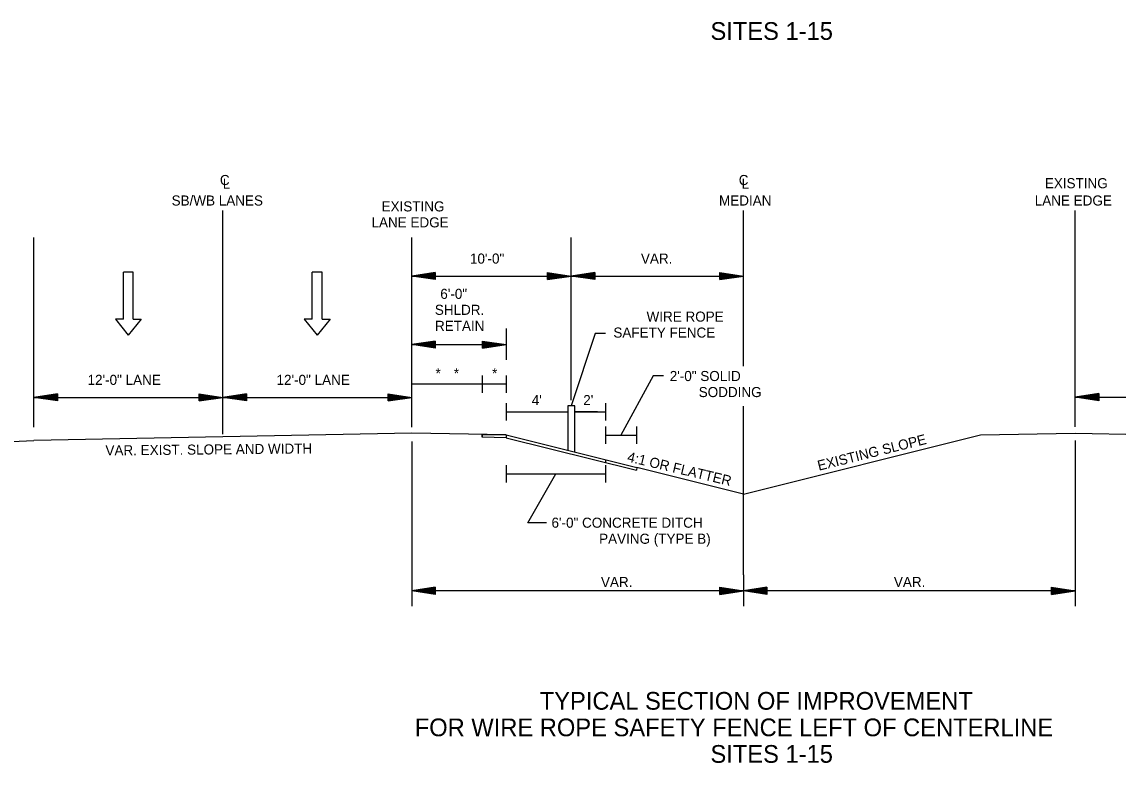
# Model space of a CAD drawing. Extents: x 1641422 to 1649187, y 577497 to 580642.
# Drawn here: x 1645133 to 1646438, y 578840 to 579722 of the extents above; entities that cross this region are included whole.
import ezdxf

# ---------------------------------------------------------------- set-up
doc = ezdxf.new("R2010")
doc.units = 0
doc.layers.add('Default', color=7, linetype='Continuous')
doc.layers.add('R_Draft', color=7, linetype='Continuous')

msp = doc.modelspace()

# ---------------------------------------------------------------- linework, layer by layer
at = {"layer": 'Default'}
for p, q in [((1645790.8, 579264.9), (1645782.7, 579264.9)), ((1645782.7, 579264.9), (1645782.7, 579211.8)), ((1645782.7, 579261.9), (1645782.7, 579254.7)), ((1645790.8, 579209.7), (1645790.8, 579264.9)), ((1645709.3, 579257.7), (1645782.7, 579257.7)), ((1645815.3, 579257.7), (1645790.8, 579257.7)), ((1645790.8, 579257.7), (1645827.5, 579257.7)), ((1645818.1, 579257.7), (1645793.6, 579257.7)), ((1645709.3, 579230.1), (1645680.8, 579230.7)), ((1645680.8, 579230.7), (1645680.8, 579227.5)), ((1645709.3, 579230.1), (1645865, 579191.2)), ((1645709.3, 579230.1), (1645709.3, 579226.9)), ((1645709.3, 579226.9), (1645864.3, 579188.2)), ((1645827.5, 579229.7), (1645864.3, 579229.7)), ((1645991.7, 579159.5), (1646274.2, 579230.1)), ((1645865, 579191.2), (1645864.3, 579188.2)), ((1645991.7, 579159.5), (1645865, 579191.2))]:
    msp.add_line(p, q, dxfattribs=at)
msp.add_lwpolyline([(1645709.2, 579226.9), (1645680.8, 579227.5), (1645680.8, 579230.7), (1645709.3, 579230.1)], close=True, dxfattribs=at)
at = {"layer": 'R_Draft'}
for p, q in [((1645371.8, 579231.2), (1645371.8, 579497.2)), ((1645991.7, 579311.9), (1645991.7, 579497.2)), ((1646386.7, 579239.8), (1646386.7, 579497.2)), ((1645146.8, 579239.5), (1645146.8, 579465.2)), ((1645596.8, 579239.5), (1645596.8, 579465.2)), ((1645786.8, 579271.7), (1645786.8, 579465.2)), ((1645265.2, 579423.9), (1645253.5, 579423.9)), ((1645253.5, 579367.8), (1645253.5, 579423.9)), ((1645265.2, 579367.8), (1645265.2, 579423.9)), ((1645490.2, 579423.9), (1645478.4, 579423.9)), ((1645478.4, 579367.8), (1645478.4, 579423.9)), ((1645490.2, 579367.8), (1645490.2, 579423.9)), ((1645624.9, 579423.4), (1645596.8, 579419.2)), ((1645624.9, 579415), (1645596.8, 579419.2)), ((1645596.8, 579419.2), (1645784.3, 579419.2)), ((1645624.9, 579422.7), (1645601.5, 579419.2)), ((1645624.9, 579415.7), (1645601.5, 579419.2)), ((1645624.9, 579422), (1645606.3, 579419.2)), ((1645624.9, 579416.4), (1645606.3, 579419.2)), ((1645624.9, 579421.3), (1645611, 579419.2)), ((1645624.9, 579417.1), (1645611, 579419.2)), ((1645624.9, 579420.5), (1645615.8, 579419.2)), ((1645624.9, 579417.8), (1645615.8, 579419.2)), ((1645624.9, 579419.8), (1645620.4, 579419.2)), ((1645624.9, 579418.5), (1645620.4, 579419.2)), ((1645624.9, 579423.4), (1645624.9, 579415)), ((1645758.6, 579423.4), (1645786.8, 579419.2)), ((1645758.6, 579415), (1645758.6, 579423.4)), ((1645758.6, 579422.7), (1645782.1, 579419.2)), ((1645758.6, 579422), (1645777.2, 579419.2)), ((1645758.6, 579421.3), (1645772.6, 579419.2)), ((1645758.6, 579420.6), (1645767.8, 579419.2)), ((1645758.6, 579419.8), (1645763.1, 579419.2)), ((1645758.6, 579415), (1645786.8, 579419.2)), ((1645758.6, 579417.8), (1645767.8, 579419.2)), ((1645758.6, 579416.4), (1645777.2, 579419.2)), ((1645758.6, 579415.7), (1645782.1, 579419.2)), ((1645758.6, 579417.1), (1645772.6, 579419.2)), ((1645758.6, 579418.5), (1645763.1, 579419.2)), ((1645814.9, 579423.4), (1645786.8, 579419.2)), ((1645814.9, 579415), (1645786.8, 579419.2)), ((1645786.8, 579419.2), (1645991.7, 579419.2)), ((1645814.9, 579422.7), (1645791.5, 579419.2)), ((1645814.9, 579415.7), (1645791.5, 579419.2)), ((1645814.9, 579422), (1645796.3, 579419.2)), ((1645814.9, 579416.4), (1645796.3, 579419.2)), ((1645814.9, 579421.3), (1645801, 579419.2)), ((1645814.9, 579417.1), (1645801, 579419.2)), ((1645814.9, 579420.5), (1645805.8, 579419.2)), ((1645814.9, 579417.8), (1645805.8, 579419.2)), ((1645814.9, 579419.8), (1645810.4, 579419.2)), ((1645814.9, 579418.5), (1645810.4, 579419.2)), ((1645814.9, 579423.4), (1645814.9, 579415)), ((1645963.6, 579423.4), (1645991.7, 579419.2)), ((1645963.6, 579415), (1645963.6, 579423.4)), ((1645963.6, 579422.7), (1645987, 579419.2)), ((1645963.6, 579422), (1645982.2, 579419.2)), ((1645963.6, 579421.3), (1645977.5, 579419.2)), ((1645963.6, 579420.6), (1645972.7, 579419.2)), ((1645963.6, 579419.8), (1645968, 579419.2)), ((1645963.6, 579415), (1645991.7, 579419.2)), ((1645963.6, 579417.8), (1645972.7, 579419.2)), ((1645963.6, 579416.4), (1645982.2, 579419.2)), ((1645963.6, 579415.7), (1645987, 579419.2)), ((1645963.6, 579417.1), (1645977.5, 579419.2)), ((1645963.6, 579418.5), (1645968, 579419.2)), ((1645709.3, 579356.9), (1645709.3, 579319.4)), ((1645624.9, 579341.9), (1645596.8, 579337.7)), ((1645624.9, 579341.2), (1645601.5, 579337.7)), ((1645624.9, 579340.5), (1645606.3, 579337.7)), ((1645624.9, 579339.8), (1645611, 579337.7)), ((1645624.9, 579341.9), (1645624.9, 579333.4)), ((1645681.1, 579341.9), (1645709.3, 579337.7)), ((1645681.1, 579333.4), (1645681.1, 579341.9)), ((1645681.1, 579341.2), (1645704.6, 579337.7)), ((1645681.1, 579340.5), (1645699.7, 579337.7)), ((1645681.1, 579339.8), (1645695.1, 579337.7)), ((1645596.8, 579337.7), (1645709.3, 579337.7)), ((1645624.9, 579333.4), (1645596.8, 579337.7)), ((1645624.9, 579334.1), (1645601.5, 579337.7)), ((1645624.9, 579334.9), (1645606.3, 579337.7)), ((1645624.9, 579335.6), (1645611, 579337.7)), ((1645624.9, 579339), (1645615.8, 579337.7)), ((1645624.9, 579336.3), (1645615.8, 579337.7)), ((1645624.9, 579338.3), (1645620.4, 579337.7)), ((1645624.9, 579337), (1645620.4, 579337.7)), ((1645681.1, 579339), (1645690.3, 579337.7)), ((1645681.1, 579338.3), (1645685.6, 579337.7)), ((1645681.1, 579333.4), (1645709.3, 579337.7)), ((1645681.1, 579336.3), (1645690.3, 579337.7)), ((1645681.1, 579334.9), (1645699.7, 579337.7)), ((1645681.1, 579334.1), (1645704.6, 579337.7)), ((1645681.1, 579335.6), (1645695.1, 579337.7)), ((1645681.1, 579337), (1645685.6, 579337.7)), ((1645680.8, 579300.8), (1645680.8, 579280.2)), ((1645709.3, 579300.8), (1645709.3, 579280.2)), ((1645680.8, 579290.5), (1645596.8, 579290.5)), ((1645709.3, 579290.5), (1645680.8, 579290.5)), ((1645175, 579279), (1645146.8, 579274.8)), ((1645146.8, 579274.8), (1645371.8, 579274.8)), ((1645175, 579270.6), (1645146.8, 579274.8)), ((1645175, 579278.3), (1645151.5, 579274.8)), ((1645175, 579271.3), (1645151.5, 579274.8)), ((1645175, 579277.6), (1645156.4, 579274.8)), ((1645175, 579272), (1645156.4, 579274.8)), ((1645175, 579276.9), (1645161, 579274.8)), ((1645175, 579272.7), (1645161, 579274.8)), ((1645175, 579276.2), (1645165.8, 579274.8)), ((1645175, 579273.4), (1645165.8, 579274.8)), ((1645175, 579275.5), (1645170.5, 579274.8)), ((1645175, 579274.2), (1645170.5, 579274.8)), ((1645175, 579279), (1645175, 579270.6)), ((1645343.7, 579279), (1645371.8, 579274.8)), ((1645343.7, 579270.6), (1645343.7, 579279)), ((1645343.7, 579278.3), (1645367.1, 579274.8)), ((1645343.7, 579277.6), (1645362.3, 579274.8)), ((1645343.7, 579276.9), (1645357.6, 579274.8)), ((1645343.7, 579276.2), (1645352.8, 579274.8)), ((1645343.7, 579275.5), (1645348.1, 579274.8)), ((1645343.7, 579270.6), (1645371.8, 579274.8)), ((1645343.7, 579273.5), (1645352.8, 579274.8)), ((1645343.7, 579272), (1645362.3, 579274.8)), ((1645343.7, 579271.3), (1645367.1, 579274.8)), ((1645343.7, 579272.7), (1645357.6, 579274.8)), ((1645343.7, 579274.2), (1645348.1, 579274.8)), ((1645399.9, 579279), (1645371.8, 579274.8)), ((1645371.8, 579274.8), (1645596.8, 579274.8)), ((1645399.9, 579270.6), (1645371.8, 579274.8)), ((1645399.9, 579278.3), (1645376.5, 579274.8)), ((1645399.9, 579271.3), (1645376.5, 579274.8)), ((1645399.9, 579277.6), (1645381.3, 579274.8)), ((1645399.9, 579272), (1645381.3, 579274.8)), ((1645399.9, 579276.9), (1645386, 579274.8)), ((1645399.9, 579272.7), (1645386, 579274.8)), ((1645399.9, 579276.2), (1645390.8, 579274.8)), ((1645399.9, 579273.4), (1645390.8, 579274.8)), ((1645399.9, 579275.5), (1645395.5, 579274.8)), ((1645399.9, 579274.2), (1645395.5, 579274.8)), ((1645399.9, 579279), (1645399.9, 579270.6)), ((1645568.6, 579279), (1645596.8, 579274.8)), ((1645568.6, 579270.6), (1645568.6, 579279)), ((1645568.6, 579278.3), (1645592.1, 579274.8)), ((1645568.6, 579277.6), (1645587.2, 579274.8)), ((1645568.6, 579276.9), (1645582.6, 579274.8)), ((1645568.6, 579276.2), (1645577.8, 579274.8)), ((1645568.6, 579275.5), (1645573.1, 579274.8)), ((1645568.6, 579270.6), (1645596.8, 579274.8)), ((1645568.6, 579273.5), (1645577.8, 579274.8)), ((1645568.6, 579272), (1645587.2, 579274.8)), ((1645568.6, 579271.3), (1645592.1, 579274.8)), ((1645568.6, 579272.7), (1645582.6, 579274.8)), ((1645568.6, 579274.2), (1645573.1, 579274.8)), ((1646414.8, 579279.4), (1646386.7, 579275.1)), ((1646386.7, 579275.1), (1646611.7, 579275.1)), ((1646414.8, 579270.9), (1646386.7, 579275.1)), ((1646414.8, 579278.7), (1646391.4, 579275.1)), ((1646414.8, 579271.6), (1646391.4, 579275.1)), ((1646414.8, 579277.9), (1646396.2, 579275.1)), ((1646414.8, 579272.3), (1646396.2, 579275.1)), ((1646414.8, 579277.2), (1646400.9, 579275.1)), ((1646414.8, 579273), (1646400.9, 579275.1)), ((1646414.8, 579276.5), (1646405.7, 579275.1)), ((1646414.8, 579273.8), (1646405.7, 579275.1)), ((1646414.8, 579275.8), (1646410.4, 579275.1)), ((1646414.8, 579274.5), (1646410.4, 579275.1)), ((1646414.8, 579279.4), (1646414.8, 579270.9)), ((1645709.3, 579268), (1645709.3, 579247.4)), ((1645827.5, 579268), (1645827.5, 579247.4)), ((1645991.7, 579063.8), (1645991.7, 579264.5)), ((1645827.5, 579240), (1645827.5, 579219.4)), ((1645864.3, 579240), (1645864.3, 579219.4)), ((1644996.3, 579217.4), (1645146.9, 579223.4)), ((1645371.8, 579227.9), (1645146.9, 579223.4)), ((1645596.8, 579232.4), (1645371.8, 579227.9)), ((1645709.3, 579230.1), (1645596.8, 579232.4)), ((1645596.8, 579222.4), (1645596.8, 579026.3)), ((1646274.2, 579230.1), (1646386.7, 579232.4)), ((1646386.7, 579232.4), (1646611.7, 579227.9)), ((1646386.7, 579223.4), (1646386.7, 579026.3)), ((1645827.5, 579200.6), (1645827.5, 579197.4)), ((1645709.3, 579194.1), (1645709.3, 579173.5)), ((1645709.3, 579183.8), (1645827.5, 579183.8)), ((1645827.5, 579194.1), (1645827.5, 579173.5)), ((1645991.7, 579063.8), (1645991.7, 579026.3)), ((1645624.9, 579048.8), (1645596.8, 579044.6)), ((1645991.7, 579044.6), (1645596.8, 579044.6)), ((1645624.9, 579040.3), (1645596.8, 579044.6)), ((1645624.9, 579048.1), (1645601.5, 579044.6)), ((1645624.9, 579041), (1645601.5, 579044.6)), ((1645624.9, 579047.4), (1645606.3, 579044.6)), ((1645624.9, 579041.8), (1645606.3, 579044.6)), ((1645624.9, 579046.7), (1645611, 579044.6)), ((1645624.9, 579042.5), (1645611, 579044.6)), ((1645624.9, 579045.9), (1645615.8, 579044.6)), ((1645624.9, 579043.2), (1645615.8, 579044.6)), ((1645624.9, 579045.2), (1645620.4, 579044.6)), ((1645624.9, 579043.9), (1645620.4, 579044.6)), ((1645624.9, 579048.8), (1645624.9, 579040.3)), ((1645737.4, 579044.6), (1645709.3, 579044.6)), ((1645963.6, 579048.8), (1645991.7, 579044.6)), ((1645963.6, 579040.3), (1645963.6, 579048.8)), ((1645963.6, 579048.1), (1645987, 579044.6)), ((1645963.6, 579047.4), (1645982.2, 579044.6)), ((1645963.6, 579046.7), (1645977.5, 579044.6)), ((1645963.6, 579045.9), (1645972.7, 579044.6)), ((1645963.6, 579045.2), (1645968, 579044.6)), ((1645963.6, 579040.3), (1645991.7, 579044.6)), ((1645963.6, 579043.2), (1645972.7, 579044.6)), ((1645963.6, 579041.8), (1645982.2, 579044.6)), ((1645963.6, 579041), (1645987, 579044.6)), ((1645963.6, 579042.5), (1645977.5, 579044.6)), ((1645963.6, 579043.9), (1645968, 579044.6)), ((1646019.8, 579048.8), (1645991.7, 579044.6)), ((1646386.7, 579044.6), (1645991.7, 579044.6)), ((1646019.8, 579040.3), (1645991.7, 579044.6)), ((1646019.8, 579048.1), (1645996.4, 579044.6)), ((1646019.8, 579041), (1645996.4, 579044.6)), ((1646019.8, 579047.4), (1646001.3, 579044.6)), ((1646019.8, 579041.8), (1646001.3, 579044.6)), ((1646019.8, 579046.7), (1646005.9, 579044.6)), ((1646019.8, 579042.5), (1646005.9, 579044.6)), ((1646019.8, 579045.9), (1646010.7, 579044.6)), ((1646019.8, 579043.2), (1646010.7, 579044.6)), ((1646019.8, 579045.2), (1646015.4, 579044.6)), ((1646019.8, 579043.9), (1646015.4, 579044.6)), ((1646019.8, 579048.8), (1646019.8, 579040.3)), ((1646358.6, 579048.8), (1646386.7, 579044.6)), ((1646358.6, 579040.3), (1646358.6, 579048.8)), ((1646358.6, 579048.1), (1646382, 579044.6)), ((1646358.6, 579047.4), (1646377.1, 579044.6)), ((1646358.6, 579046.7), (1646372.5, 579044.6)), ((1646358.6, 579045.9), (1646367.7, 579044.6)), ((1646358.6, 579045.2), (1646363, 579044.6)), ((1646358.6, 579040.3), (1646386.7, 579044.6)), ((1646358.6, 579043.2), (1646367.7, 579044.6)), ((1646358.6, 579041.8), (1646377.1, 579044.6)), ((1646358.6, 579041), (1646382, 579044.6)), ((1646358.6, 579042.5), (1646372.5, 579044.6)), ((1646358.6, 579043.9), (1646363, 579044.6))]:
    msp.add_line(p, q, dxfattribs=at)
for points in [[(1645253.5, 579367.8), (1645243.9, 579367.8), (1645259.3, 579349)], [(1645265.2, 579367.8), (1645274.8, 579367.8), (1645259.3, 579349)], [(1645478.4, 579367.8), (1645468.8, 579367.8), (1645484.3, 579349)], [(1645490.2, 579367.8), (1645499.8, 579367.8), (1645484.3, 579349)], [(1645827.6, 579351), (1645815.3, 579350.9), (1645786.8, 579264.9)], [(1645896.7, 579300.4), (1645884.4, 579300.4), (1645845.9, 579229.7)], [(1645757.1, 579125.7), (1645735.1, 579125.7), (1645768.4, 579183.8)]]:
    msp.add_lwpolyline(points, dxfattribs=at)

# ---------------------------------------------------------------- texts
at = {"layer": 'Default'}
for s, p in [('*', (1645625.2, 579297.5)), ('*', (1645646.9, 579297.5)), ('*', (1645692.5, 579297.5)), ("4'", (1645739.7, 579265.6)), ("2'", (1645801, 579265.6))]:
    msp.add_text(s, height=12, dxfattribs=at).set_placement(p)
at = {"layer": 'R_Draft'}
for s, height, p in [('SITES 1-15', 21.09, (1645952.5, 579700.4)), ('C', 12, (1645368.4, 579527.6)), ('L', 12, (1645371.8, 579523.2)), ('C', 12, (1645986.2, 579527.6)), ('L', 12, (1645989.6, 579523.1)), ('EXISTING', 12, (1646350.6, 579523.8)), ('SB/WB LANES', 12, (1645310.9, 579503.2)), ('MEDIAN', 12, (1645962.7, 579503.2)), ('LANE EDGE', 12, (1646338.6, 579503.2)), ('EXISTING', 12, (1645560.9, 579496.2)), ('LANE EDGE', 12, (1645548.9, 579477.2)), ('10\'-0"', 12, (1645666.1, 579434.1)), ('VAR.', 12, (1645869.7, 579434.1)), ('6\'-0"', 12, (1645630.8, 579392.1)), ('SHLDR.', 12, (1645624.3, 579373.1)), ('RETAIN', 12, (1645624.5, 579354)), ('WIRE ROPE', 12, (1645876.4, 579365)), ('SAFETY FENCE', 12, (1645836.9, 579346)), ('12\'-0" LANE', 12, (1645210.8, 579289.7)), ('12\'-0" LANE', 12, (1645435.8, 579289.7)), ('2\'-0" SOLID', 12, (1645904, 579294.3)), ('SODDING', 12, (1645938.5, 579275.2)), ('6\'-0" CONCRETE DITCH', 12, (1645763.2, 579119.7)), ('PAVING (TYPE B)', 12, (1645819.9, 579100.6)), ('VAR.', 12, (1645822.1, 579049.1)), ('VAR.', 12, (1646170.9, 579049.1)), ('TYPICAL SECTION OF IMPROVEMENT', 21.094, (1645749.2, 578903.1)), ('FOR WIRE ROPE SAFETY FENCE LEFT OF CENTERLINE', 21.094, (1645600.4, 578871.5)), ('SITES 1-15', 21.09, (1645952.5, 578839.9))]:
    msp.add_text(s, height=height, dxfattribs=at).set_placement(p)
for s, rotation, p in [('EXISTING SLOPE', 14.003, (1646081.6, 579187.5)), ('VAR. EXIST. SLOPE AND WIDTH', 0.5537, (1645232.2, 579205.7)), ('4:1 OR FLATTER', 346.5915, (1645852.7, 579198.7))]:
    msp.add_text(s, height=12, rotation=rotation, dxfattribs=at).set_placement(p)

doc.saveas('drawing.dxf')
